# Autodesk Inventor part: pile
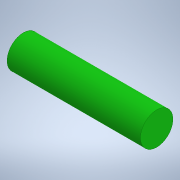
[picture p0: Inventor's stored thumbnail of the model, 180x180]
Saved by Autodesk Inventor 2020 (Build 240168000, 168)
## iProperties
Created: 2021-10
Part Number: pile
Material: PVC, non plastifié
Document SubType Name: Modeling
Designer: bruno
Density: 2.33661 g/cm^3
Appearance: Vert foncé
Mass: 44 g
Surface Area: 46.9354 cm^2
Volume: 18.8307 cm^3
Author: bruno
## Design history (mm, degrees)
sketch "Esquisse1"
  geometry: C1 r 9 at (0, 0); 1 further point
  constraints: 1 centre point, 1 coincident
  dimensions: "d0" = 18 diameter of C1
extrude "Extrusion1" new body sketch "Esquisse1" distance "d1" = 74; taper "d2" = 0 deg
node "Solide1"
